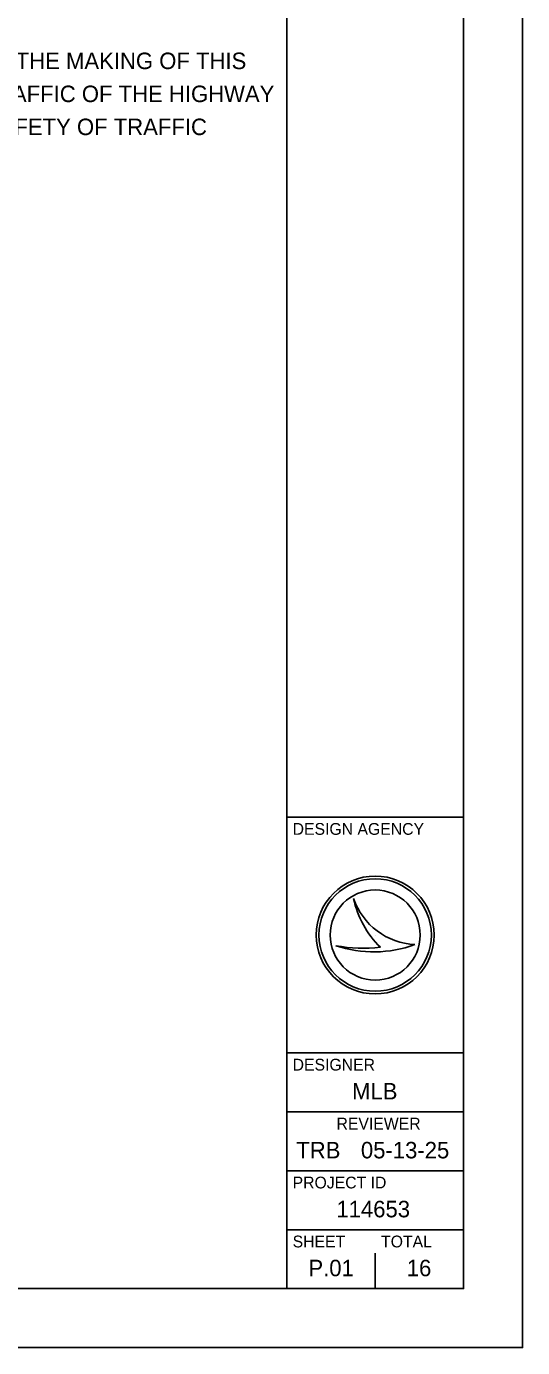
# Model space of a CAD drawing. Extents: x 0 to 34, y 0 to 22.
# Drawn here: x 29.79 to 34, y 0 to 11.21 of the extents above; entities that cross this region are included whole.
import ezdxf

# ---------------------------------------------------------------- set-up
doc = ezdxf.new("R2010")
doc.units = 0
for name, color, linetype in [('SH_Border', 7, 'Continuous'), ('SH_Cut_Line', 7, 'Continuous'), ('SH_Data', 7, 'Continuous')]:
    doc.layers.add(name, color=color, linetype=linetype)

msp = doc.modelspace()

# ---------------------------------------------------------------- linework, layer by layer
at = {"layer": 'SH_Border'}
for p, q in [((32, 0.5), (32, 21.5)), ((32, 4.5), (33.5, 4.5)), ((32, 2.5), (33.5, 2.5)), ((32, 2), (33.5, 2)), ((32, 1.5), (33.5, 1.5)), ((32, 1), (33.5, 1))]:
    msp.add_line(p, q, dxfattribs=at)
msp.add_lwpolyline([(1.5, 21.5), (33.5, 21.5), (33.5, 0.5), (1.5, 0.5)], close=True, dxfattribs=at)
at = {"layer": 'SH_Cut_Line'}
msp.add_lwpolyline([(0, 0), (34, 0), (34, 22), (0, 22)], close=True, dxfattribs=at)
at = {"layer": 'SH_Data'}
for p, q in [((32.567, 3.81), (32.567, 3.81)), ((32.75, 3.5), (32.75, 3.5)), ((32.417, 3.41), (32.417, 3.41)), ((33.087, 3.419), (33.087, 3.419)), ((32.75, 0.5), (32.75, 0.8)), ((32.375, 0.675), (32.375, 0.675))]:
    msp.add_line(p, q, dxfattribs=at)
for radius in [0.5, 0.477, 0.477, 0.382]:
    msp.add_circle((32.75, 3.5), radius, dxfattribs=at)
for centre, radius, start, end in [((33.116, 3.998), 0.58, 198.9257, 198.9319), ((33.347, 3.97), 0.796, 191.6379, 191.6421), ((33.116, 3.998), 0.58, 198.9319, 267.1657), ((33.347, 3.97), 0.796, 191.6421, 226.0947), ((32.739, 4.37), 1.013, 251.4576, 290.0832), ((32.648, 4.654), 1.266, 259.4964, 259.4995), ((32.739, 4.37), 1.013, 251.4527, 251.4576), ((32.648, 4.654), 1.266, 259.4995, 276.6672)]:
    msp.add_arc(centre, radius, start, end, dxfattribs=at)

# ---------------------------------------------------------------- texts
for s, height, p in [(' I HEREBY APPROVE THESE PLANS AND DECLARE THAT THE MAKING OF THIS', 0.14, (24.5, 10.846)), ('IMPROVEMENT WILL NOT REQUIRE THE CLOSING TO TRAFFIC OF THE HIGHWAY', 0.14, (24.5, 10.566)), ('AND THAT PROVISIONS FOR THE MAINTENANCE AND SAFETY OF TRAFFIC', 0.14, (24.5, 10.286)), ('DESIGN AGENCY', 0.1, (32.05, 4.35)), ('DESIGNER', 0.1, (32.05, 2.35)), ('MLB', 0.14, (32.554, 2.105)), ('REVIEWER', 0.1, (32.422, 1.85)), ('TRB', 0.14, (32.081, 1.605)), ('05-13-25', 0.14, (32.629, 1.605)), ('PROJECT ID', 0.1, (32.05, 1.35)), ('114653', 0.14, (32.421, 1.105)), ('SHEET', 0.1, (32.05, 0.85)), ('TOTAL', 0.1, (32.8, 0.85)), ('P.01', 0.14, (32.184, 0.605)), ('16', 0.14, (33.018, 0.605))]:
    msp.add_text(s, height=height, dxfattribs=at).set_placement(p)

doc.saveas('drawing.dxf')
